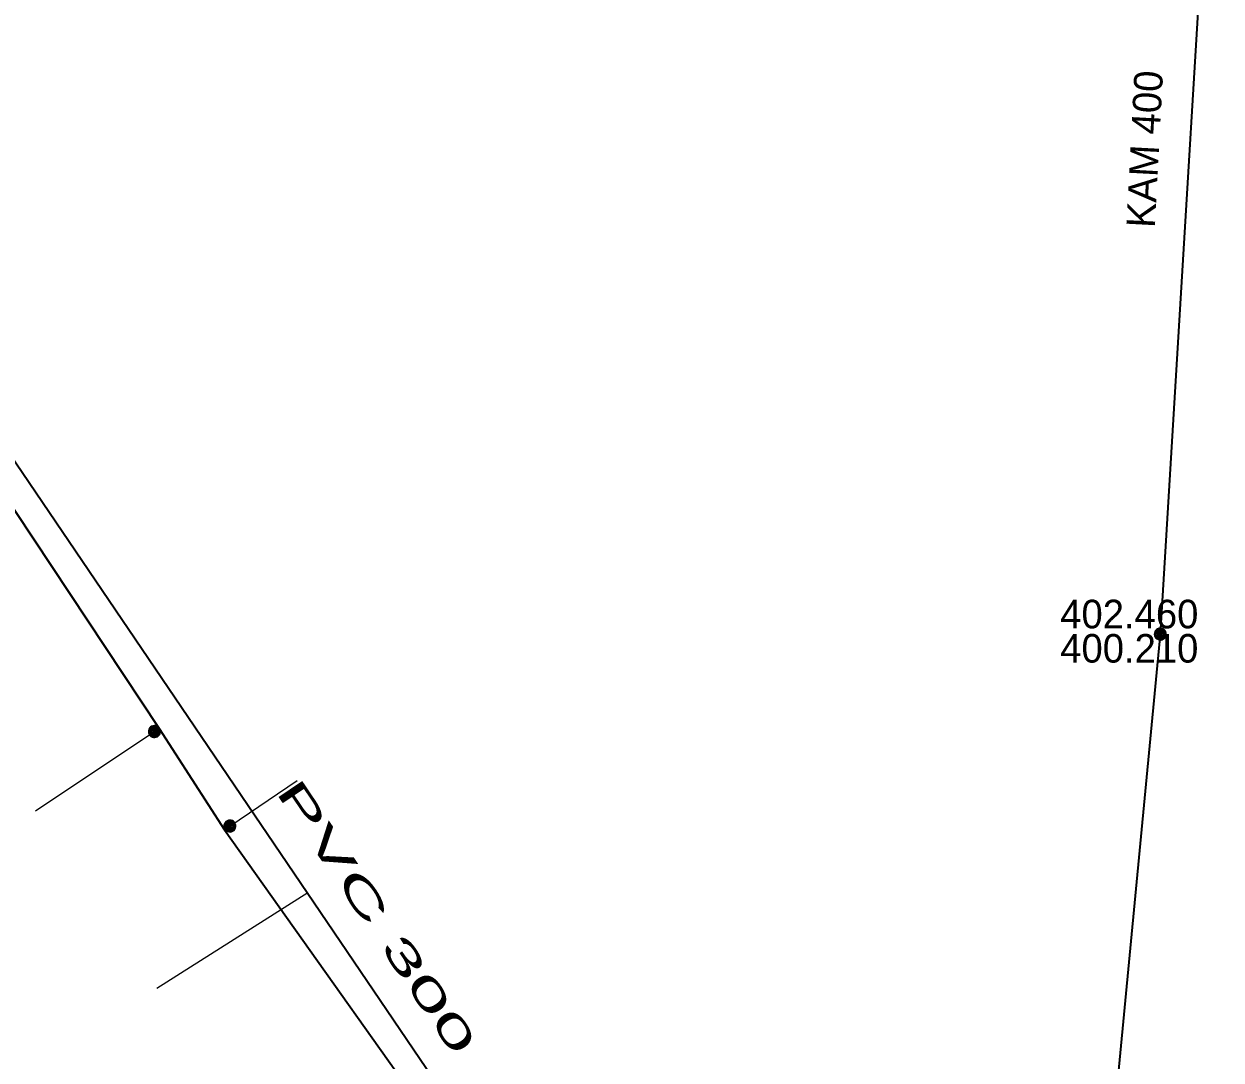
# Model space of a CAD drawing. Extents: x -873619 to -867639, y -1015082 to -1012326.
# Drawn here: x -867913.44 to -867867.37, y -1012899.86 to -1012859.98 of the extents above; entities that cross this region are included whole.
import ezdxf

# ---------------------------------------------------------------- set-up
doc = ezdxf.new("R2010")
doc.units = 0
doc.header["$LTSCALE"] = 0.44
for name, color, linetype, lineweight in [('1', 7, 'Continuous', 13), ('12', 7, 'Continuous', 13), ('21', 7, 'Continuous', 35), ('23', 7, 'Continuous', 25), ('3', 7, 'Continuous', 25), ('32', 7, 'Continuous', 13)]:
    doc.layers.add(name, color=color, linetype=linetype, lineweight=lineweight)

msp = doc.modelspace()

# ---------------------------------------------------------------- linework, layer by layer
at = {"layer": '1', "lineweight": 35}
msp.add_lwpolyline([(-867979.181, -1012799.683), (-867972.83, -1012801.89), (-867965.59, -1012804.78), (-867963.787, -1012807.409), (-867948.768, -1012827.087), (-867948.538, -1012827.407), (-867943.513, -1012834.828), (-867938.476, -1012842.701), (-867934.013, -1012848.778), (-867931.689, -1012852.506), (-867924.702, -1012862.569), (-867923.496, -1012864.901), (-867916.531, -1012874.592), (-867908.231, -1012887.091), (-867905.717, -1012890.99), (-867899.122, -1012900.29), (-867892.55, -1012910.082), (-867889.71, -1012914.412), (-867888.18, -1012916.7), (-867891.84, -1012919), (-867886.89, -1012927.31), (-867886.728, -1012931.158)], dxfattribs=at)
at = {"layer": '12'}
for points in [[(-867908.184, -1012887.213), (-867908.19, -1012887.161), (-867908.207, -1012887.111), (-867908.236, -1012887.067), (-867908.273, -1012887.03), (-867908.318, -1012887.003), (-867908.368, -1012886.986), (-867908.421, -1012886.982), (-867908.473, -1012886.989), (-867908.522, -1012887.008), (-867908.565, -1012887.037), (-867908.601, -1012887.076), (-867908.627, -1012887.121), (-867908.643, -1012887.172), (-867908.646, -1012887.224), (-867908.638, -1012887.276), (-867908.618, -1012887.325), (-867908.587, -1012887.368), (-867908.548, -1012887.402), (-867908.502, -1012887.428), (-867908.451, -1012887.442), (-867908.398, -1012887.444), (-867908.347, -1012887.434), (-867908.299, -1012887.413), (-867908.256, -1012887.382), (-867908.222, -1012887.341), (-867908.198, -1012887.295), (-867908.186, -1012887.244)], [(-867908.214, -1012887.213), (-867908.22, -1012887.164), (-867908.237, -1012887.118), (-867908.265, -1012887.078), (-867908.302, -1012887.046), (-867908.346, -1012887.024), (-867908.394, -1012887.013), (-867908.443, -1012887.013), (-867908.49, -1012887.026), (-867908.533, -1012887.05), (-867908.569, -1012887.083), (-867908.596, -1012887.124), (-867908.612, -1012887.171), (-867908.616, -1012887.22), (-867908.609, -1012887.268), (-867908.59, -1012887.313), (-867908.56, -1012887.353), (-867908.522, -1012887.384), (-867908.478, -1012887.404), (-867908.43, -1012887.414), (-867908.381, -1012887.412), (-867908.334, -1012887.397), (-867908.291, -1012887.372), (-867908.257, -1012887.338), (-867908.231, -1012887.296), (-867908.217, -1012887.249)], [(-867908.244, -1012887.213), (-867908.25, -1012887.168), (-867908.267, -1012887.126), (-867908.295, -1012887.091), (-867908.331, -1012887.064), (-867908.373, -1012887.047), (-867908.418, -1012887.042), (-867908.463, -1012887.048), (-867908.504, -1012887.067), (-867908.539, -1012887.095), (-867908.566, -1012887.132), (-867908.582, -1012887.174), (-867908.586, -1012887.219), (-867908.579, -1012887.264), (-867908.56, -1012887.305), (-867908.531, -1012887.339), (-867908.494, -1012887.365), (-867908.451, -1012887.381), (-867908.406, -1012887.384), (-867908.361, -1012887.376), (-867908.321, -1012887.356), (-867908.287, -1012887.327), (-867908.261, -1012887.289), (-867908.247, -1012887.246)], [(-867908.274, -1012887.213), (-867908.279, -1012887.172), (-867908.297, -1012887.135), (-867908.324, -1012887.104), (-867908.359, -1012887.083), (-867908.399, -1012887.072), (-867908.44, -1012887.074), (-867908.479, -1012887.087), (-867908.513, -1012887.111), (-867908.538, -1012887.143), (-867908.553, -1012887.181), (-867908.556, -1012887.222), (-867908.548, -1012887.262), (-867908.528, -1012887.298), (-867908.499, -1012887.327), (-867908.462, -1012887.346), (-867908.422, -1012887.354), (-867908.381, -1012887.35), (-867908.343, -1012887.335), (-867908.311, -1012887.309), (-867908.288, -1012887.275), (-867908.275, -1012887.236)], [(-867908.304, -1012887.213), (-867908.309, -1012887.177), (-867908.327, -1012887.145), (-867908.353, -1012887.12), (-867908.387, -1012887.105), (-867908.423, -1012887.102), (-867908.458, -1012887.11), (-867908.489, -1012887.13), (-867908.512, -1012887.158), (-867908.525, -1012887.192), (-867908.525, -1012887.229), (-867908.514, -1012887.264), (-867908.493, -1012887.293), (-867908.463, -1012887.314), (-867908.428, -1012887.324), (-867908.391, -1012887.322), (-867908.357, -1012887.308), (-867908.33, -1012887.285), (-867908.311, -1012887.253), (-867908.304, -1012887.218)], [(-867908.334, -1012887.213), (-867908.339, -1012887.182), (-867908.356, -1012887.156), (-867908.382, -1012887.139), (-867908.412, -1012887.132), (-867908.443, -1012887.136), (-867908.47, -1012887.153), (-867908.488, -1012887.177), (-867908.496, -1012887.208), (-867908.492, -1012887.238), (-867908.477, -1012887.266), (-867908.453, -1012887.285), (-867908.423, -1012887.294), (-867908.392, -1012887.291), (-867908.364, -1012887.277), (-867908.344, -1012887.253), (-867908.334, -1012887.224)], [(-867908.364, -1012887.213), (-867908.369, -1012887.189), (-867908.386, -1012887.171), (-867908.409, -1012887.162), (-867908.433, -1012887.165), (-867908.454, -1012887.179), (-867908.465, -1012887.201), (-867908.465, -1012887.226), (-867908.453, -1012887.247), (-867908.433, -1012887.261), (-867908.408, -1012887.264), (-867908.385, -1012887.255), (-867908.369, -1012887.237)], [(-867908.394, -1012887.213), (-867908.399, -1012887.198), (-867908.414, -1012887.192), (-867908.429, -1012887.196), (-867908.436, -1012887.21), (-867908.432, -1012887.225), (-867908.419, -1012887.234), (-867908.404, -1012887.231), (-867908.394, -1012887.219)], [(-867905.279, -1012890.85), (-867905.285, -1012890.798), (-867905.302, -1012890.748), (-867905.331, -1012890.704), (-867905.368, -1012890.667), (-867905.413, -1012890.64), (-867905.463, -1012890.623), (-867905.516, -1012890.619), (-867905.568, -1012890.626), (-867905.617, -1012890.645), (-867905.66, -1012890.674), (-867905.696, -1012890.713), (-867905.722, -1012890.758), (-867905.738, -1012890.809), (-867905.741, -1012890.861), (-867905.733, -1012890.913), (-867905.713, -1012890.962), (-867905.682, -1012891.005), (-867905.643, -1012891.039), (-867905.597, -1012891.065), (-867905.546, -1012891.079), (-867905.493, -1012891.081), (-867905.442, -1012891.071), (-867905.394, -1012891.05), (-867905.351, -1012891.019), (-867905.317, -1012890.978), (-867905.293, -1012890.932), (-867905.281, -1012890.881)], [(-867905.309, -1012890.85), (-867905.315, -1012890.801), (-867905.332, -1012890.755), (-867905.36, -1012890.715), (-867905.397, -1012890.683), (-867905.441, -1012890.661), (-867905.489, -1012890.65), (-867905.538, -1012890.65), (-867905.585, -1012890.663), (-867905.628, -1012890.687), (-867905.664, -1012890.72), (-867905.691, -1012890.761), (-867905.707, -1012890.808), (-867905.711, -1012890.857), (-867905.704, -1012890.905), (-867905.685, -1012890.95), (-867905.655, -1012890.99), (-867905.617, -1012891.021), (-867905.573, -1012891.041), (-867905.525, -1012891.051), (-867905.476, -1012891.049), (-867905.429, -1012891.034), (-867905.386, -1012891.009), (-867905.352, -1012890.975), (-867905.326, -1012890.933), (-867905.312, -1012890.886)], [(-867905.339, -1012890.85), (-867905.345, -1012890.805), (-867905.362, -1012890.763), (-867905.39, -1012890.728), (-867905.426, -1012890.701), (-867905.468, -1012890.684), (-867905.513, -1012890.679), (-867905.558, -1012890.685), (-867905.599, -1012890.704), (-867905.634, -1012890.732), (-867905.661, -1012890.769), (-867905.677, -1012890.811), (-867905.681, -1012890.856), (-867905.674, -1012890.901), (-867905.655, -1012890.942), (-867905.626, -1012890.976), (-867905.589, -1012891.002), (-867905.546, -1012891.018), (-867905.501, -1012891.021), (-867905.456, -1012891.013), (-867905.416, -1012890.993), (-867905.382, -1012890.964), (-867905.356, -1012890.926), (-867905.342, -1012890.883)], [(-867905.369, -1012890.85), (-867905.374, -1012890.809), (-867905.392, -1012890.772), (-867905.419, -1012890.741), (-867905.454, -1012890.72), (-867905.494, -1012890.709), (-867905.535, -1012890.711), (-867905.574, -1012890.724), (-867905.608, -1012890.748), (-867905.633, -1012890.78), (-867905.648, -1012890.818), (-867905.651, -1012890.859), (-867905.643, -1012890.899), (-867905.623, -1012890.935), (-867905.594, -1012890.964), (-867905.557, -1012890.983), (-867905.517, -1012890.991), (-867905.476, -1012890.987), (-867905.438, -1012890.972), (-867905.406, -1012890.946), (-867905.383, -1012890.912), (-867905.37, -1012890.873)], [(-867905.399, -1012890.85), (-867905.404, -1012890.814), (-867905.422, -1012890.782), (-867905.448, -1012890.757), (-867905.482, -1012890.742), (-867905.518, -1012890.739), (-867905.553, -1012890.747), (-867905.584, -1012890.767), (-867905.607, -1012890.795), (-867905.62, -1012890.829), (-867905.62, -1012890.866), (-867905.609, -1012890.901), (-867905.588, -1012890.93), (-867905.558, -1012890.951), (-867905.523, -1012890.961), (-867905.486, -1012890.959), (-867905.452, -1012890.945), (-867905.425, -1012890.922), (-867905.406, -1012890.89), (-867905.399, -1012890.855)], [(-867905.429, -1012890.85), (-867905.434, -1012890.819), (-867905.451, -1012890.793), (-867905.477, -1012890.776), (-867905.507, -1012890.769), (-867905.538, -1012890.773), (-867905.565, -1012890.79), (-867905.583, -1012890.814), (-867905.591, -1012890.845), (-867905.587, -1012890.875), (-867905.572, -1012890.903), (-867905.548, -1012890.922), (-867905.518, -1012890.931), (-867905.487, -1012890.928), (-867905.459, -1012890.914), (-867905.439, -1012890.89), (-867905.429, -1012890.861)], [(-867905.459, -1012890.85), (-867905.464, -1012890.826), (-867905.481, -1012890.808), (-867905.504, -1012890.799), (-867905.528, -1012890.802), (-867905.549, -1012890.816), (-867905.56, -1012890.838), (-867905.56, -1012890.863), (-867905.548, -1012890.884), (-867905.528, -1012890.898), (-867905.503, -1012890.901), (-867905.48, -1012890.892), (-867905.464, -1012890.874)], [(-867905.489, -1012890.85), (-867905.494, -1012890.835), (-867905.509, -1012890.829), (-867905.524, -1012890.833), (-867905.531, -1012890.847), (-867905.527, -1012890.862), (-867905.514, -1012890.871), (-867905.499, -1012890.868), (-867905.489, -1012890.856)]]:
    msp.add_lwpolyline(points, close=True, dxfattribs=at)
at = {"layer": '21'}
msp.add_line((-867915.29, -1012874.6), (-867889.85, -1012912.11), dxfattribs=at)
msp.add_lwpolyline([(-867868.119, -1012814.87), (-867867.37, -1012844.68), (-867869.709, -1012883.46), (-867874.376, -1012932.352)], dxfattribs=at)
at = {"layer": '23'}
msp.add_line((-867902.516, -1012893.415), (-867908.32, -1012897.1), dxfattribs=at)
at = {"layer": '3'}
for points in [[(-867912.99, -1012890.263), (-867908.44, -1012887.23), (-867908.231, -1012887.091)], [(-867905.717, -1012890.99), (-867905.51, -1012890.85), (-867902.918, -1012889.095)]]:
    msp.add_lwpolyline(points, dxfattribs=at)
at = {"layer": '32'}
for points in [[(-867869.478, -1012883.46), (-867869.484, -1012883.408), (-867869.501, -1012883.358), (-867869.53, -1012883.314), (-867869.567, -1012883.277), (-867869.612, -1012883.25), (-867869.662, -1012883.233), (-867869.715, -1012883.229), (-867869.767, -1012883.236), (-867869.816, -1012883.255), (-867869.859, -1012883.284), (-867869.895, -1012883.323), (-867869.921, -1012883.368), (-867869.937, -1012883.419), (-867869.94, -1012883.471), (-867869.932, -1012883.523), (-867869.912, -1012883.572), (-867869.881, -1012883.615), (-867869.842, -1012883.649), (-867869.796, -1012883.675), (-867869.745, -1012883.689), (-867869.692, -1012883.691), (-867869.641, -1012883.681), (-867869.593, -1012883.66), (-867869.55, -1012883.629), (-867869.516, -1012883.588), (-867869.492, -1012883.542), (-867869.48, -1012883.491)], [(-867869.508, -1012883.46), (-867869.514, -1012883.411), (-867869.531, -1012883.365), (-867869.559, -1012883.325), (-867869.596, -1012883.293), (-867869.64, -1012883.271), (-867869.688, -1012883.26), (-867869.737, -1012883.26), (-867869.784, -1012883.273), (-867869.827, -1012883.297), (-867869.863, -1012883.33), (-867869.89, -1012883.371), (-867869.906, -1012883.418), (-867869.91, -1012883.467), (-867869.903, -1012883.515), (-867869.884, -1012883.56), (-867869.854, -1012883.6), (-867869.816, -1012883.631), (-867869.772, -1012883.651), (-867869.724, -1012883.661), (-867869.675, -1012883.659), (-867869.628, -1012883.644), (-867869.585, -1012883.619), (-867869.551, -1012883.585), (-867869.525, -1012883.543), (-867869.511, -1012883.496)], [(-867869.538, -1012883.46), (-867869.544, -1012883.415), (-867869.561, -1012883.373), (-867869.589, -1012883.338), (-867869.625, -1012883.311), (-867869.667, -1012883.294), (-867869.712, -1012883.289), (-867869.757, -1012883.295), (-867869.798, -1012883.314), (-867869.833, -1012883.342), (-867869.86, -1012883.379), (-867869.876, -1012883.421), (-867869.88, -1012883.466), (-867869.873, -1012883.511), (-867869.854, -1012883.552), (-867869.825, -1012883.586), (-867869.788, -1012883.612), (-867869.745, -1012883.628), (-867869.7, -1012883.631), (-867869.655, -1012883.623), (-867869.615, -1012883.603), (-867869.581, -1012883.574), (-867869.555, -1012883.536), (-867869.541, -1012883.493)], [(-867869.568, -1012883.46), (-867869.573, -1012883.419), (-867869.591, -1012883.382), (-867869.618, -1012883.351), (-867869.653, -1012883.33), (-867869.693, -1012883.319), (-867869.734, -1012883.321), (-867869.773, -1012883.334), (-867869.807, -1012883.358), (-867869.832, -1012883.39), (-867869.847, -1012883.428), (-867869.85, -1012883.469), (-867869.842, -1012883.509), (-867869.822, -1012883.545), (-867869.793, -1012883.574), (-867869.756, -1012883.593), (-867869.716, -1012883.601), (-867869.675, -1012883.597), (-867869.637, -1012883.582), (-867869.605, -1012883.556), (-867869.582, -1012883.522), (-867869.569, -1012883.483)], [(-867869.598, -1012883.46), (-867869.603, -1012883.424), (-867869.621, -1012883.392), (-867869.647, -1012883.367), (-867869.681, -1012883.352), (-867869.717, -1012883.349), (-867869.752, -1012883.357), (-867869.783, -1012883.377), (-867869.806, -1012883.405), (-867869.819, -1012883.439), (-867869.819, -1012883.476), (-867869.808, -1012883.511), (-867869.787, -1012883.54), (-867869.757, -1012883.561), (-867869.722, -1012883.571), (-867869.685, -1012883.569), (-867869.651, -1012883.555), (-867869.624, -1012883.532), (-867869.605, -1012883.5), (-867869.598, -1012883.465)], [(-867869.628, -1012883.46), (-867869.633, -1012883.429), (-867869.65, -1012883.403), (-867869.676, -1012883.386), (-867869.706, -1012883.379), (-867869.737, -1012883.383), (-867869.764, -1012883.4), (-867869.782, -1012883.424), (-867869.79, -1012883.455), (-867869.786, -1012883.485), (-867869.771, -1012883.513), (-867869.747, -1012883.532), (-867869.717, -1012883.541), (-867869.686, -1012883.538), (-867869.658, -1012883.524), (-867869.638, -1012883.5), (-867869.628, -1012883.471)], [(-867869.658, -1012883.46), (-867869.663, -1012883.436), (-867869.68, -1012883.418), (-867869.703, -1012883.409), (-867869.727, -1012883.412), (-867869.748, -1012883.426), (-867869.759, -1012883.448), (-867869.759, -1012883.473), (-867869.747, -1012883.494), (-867869.727, -1012883.508), (-867869.702, -1012883.511), (-867869.679, -1012883.502), (-867869.663, -1012883.484)], [(-867869.688, -1012883.46), (-867869.693, -1012883.445), (-867869.708, -1012883.439), (-867869.723, -1012883.443), (-867869.73, -1012883.457), (-867869.726, -1012883.472), (-867869.713, -1012883.481), (-867869.698, -1012883.478), (-867869.688, -1012883.466)]]:
    msp.add_lwpolyline(points, close=True, dxfattribs=at)

# ---------------------------------------------------------------- texts
at = {"layer": '1'}
msp.add_text('KAM 400 ', height=1.1, rotation=87, dxfattribs=at).set_placement((-867869.918, -1012867.843))
for s, p in [('402.460 ', (-867873.559, -1012883.24)), ('400.210 ', (-867873.559, -1012884.56))]:
    msp.add_text(s, height=1.1, dxfattribs=at).set_placement(p)
at = {"layer": '1', "width": 2.1}
msp.add_text('PVC 300 ', height=1.1, rotation=304, dxfattribs=at).set_placement((-867903.779, -1012889.522))

doc.saveas('drawing.dxf')
